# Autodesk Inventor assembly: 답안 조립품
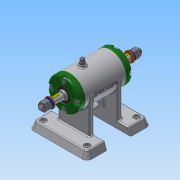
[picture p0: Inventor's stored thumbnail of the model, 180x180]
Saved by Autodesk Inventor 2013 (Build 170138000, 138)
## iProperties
Created: 2016-07
Part Number: 답안 조립품
Document SubType Name: Assembly
Designer: Administrator
Author: Administrator
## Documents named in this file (16)
- C:\Users\Administrator\Desktop\460708V1012\답안 조립품.iam
- C:\Users\Administrator\Desktop\460708V1012\1-본체.ipt
- C:\Users\Administrator\Desktop\460708V1012\V벨트풀리.ipt
- C:\Users\Administrator\Desktop\460708V1012\너트 M 8.ipt
- C:\Users\Administrator\Desktop\460708V1012\니플 M 6 x 0.75.ipt
- C:\Users\Administrator\Desktop\460708V1012\베어링 15 x 32 x 9.ipt
- C:\Users\Administrator\Desktop\460708V1012\볼트 M 6 x 8.ipt
- C:\Users\Administrator\Desktop\460708V1012\볼트 M4 x 12.ipt
- C:\Users\Administrator\Desktop\460708V1012\스퍼기어.ipt
- C:\Users\Administrator\Desktop\460708V1012\스프링와셔 8.ipt
- C:\Users\Administrator\Desktop\460708V1012\오일 실 15 25 7.ipt
- C:\Users\Administrator\Desktop\460708V1012\와셔 6x11.5.ipt
- C:\Users\Administrator\Desktop\460708V1012\와셔 8x17.ipt
- C:\Users\Administrator\Desktop\460708V1012\축.ipt
- C:\Users\Administrator\Desktop\460708V1012\커버.ipt
- C:\Users\Administrator\Desktop\460708V1012\키 3 x 3 x 12.ipt
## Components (12 placed, 4 different names)
1. 1-본체:1
2. V벨트풀리:1 — 각도:2
3. KS B 2023 6002 - 15 x 32 x 9:1
4. KS B 2023 6002 - 15 x 32 x 9:2
5. ISO 4762 M4 x 12:2
6. ISO 4762 M4 x 12:3
7. ISO 4762 M4 x 12:4
8. ISO 4762 M4 x 12:5
9. ISO 4762 M4 x 12:1
10. ISO 4762 M4 x 12:6
11. ISO 4762 M4 x 12:7
12. ISO 4762 M4 x 12:8
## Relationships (1: Angle 1)
- 각도:2 [Angle]: V벨트풀리:1
